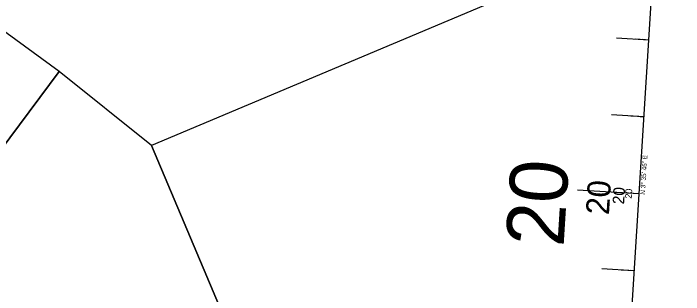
# Model space of a CAD drawing. Extents: x 2358865 to 2362945, y 393485 to 404880.
# Drawn here: x 2361585 to 2362454, y 402057 to 402421 of the extents above; entities that cross this region are included whole.
import ezdxf

# ---------------------------------------------------------------- set-up
doc = ezdxf.new("R2010")
doc.units = 0
for name, color, linetype in [('CL', 7, 'Continuous'), ('Level 11', 7, 'Continuous'), ('Level 19', 7, 'Continuous'), ('Level 21', 7, 'Continuous'), ('Level 25', 7, 'Continuous'), ('Level 27', 7, 'Continuous'), ('Level 30', 7, 'Continuous'), ('Level 37', 7, 'Continuous'), ('Level 39', 7, 'Continuous'), ('Level 41', 7, 'Continuous'), ('Level 48', 7, 'Continuous'), ('Level 63', 7, 'Continuous')]:
    doc.layers.add(name, color=color, linetype=linetype)

msp = doc.modelspace()

# ---------------------------------------------------------------- linework, layer by layer
at = {"layer": 'CL'}
msp.add_line((2362381, 401942.38), (2362564.78, 404866.59), dxfattribs=at)
msp.add_arc((2360608.55, 400955.34), 1370, 315.75191, 87.32696, dxfattribs=at)
at = {"layer": 'Level 11'}
msp.add_arc((2360631.17, 400937.8), 1389.46, 44.67453, 59.73673, dxfattribs=at)
at = {"layer": 'Level 19'}
for centre, radius, start, end in [((2360631.17, 400937.8), 1385.46, 44.67453, 59.73673), ((2360586.69, 400973.8), 1353.95, 42.30084, 57.36334)]:
    msp.add_arc(centre, radius, start, end, dxfattribs=at)
at = {"layer": 'Level 25'}
for p, q in [((2362408.93, 402386.76), (2362403.94, 402387.07)), ((2362402.66, 402286.96), (2362397.67, 402287.27)), ((2362396.38, 402187.15), (2362388.4, 402187.66)), ((2362390.11, 402087.35), (2362385.12, 402087.66))]:
    msp.add_line(p, q, dxfattribs=at)
at = {"layer": 'Level 27'}
msp.add_arc((2360608.55, 400955.34), 1310, 18.31889, 61.65271, dxfattribs=at)
at = {"layer": 'Level 30'}
for p, q in [((2362408.93, 402386.76), (2362400.44, 402387.29)), ((2362402.66, 402286.96), (2362394.17, 402287.49)), ((2362396.38, 402187.15), (2362380.41, 402188.16)), ((2362390.11, 402087.35), (2362381.63, 402087.88))]:
    msp.add_line(p, q, dxfattribs=at)
at = {"layer": 'Level 37'}
for centre, radius, start, end in [((2360586.69, 400973.8), 1365.95, 42.30084, 56.86254), ((2360631.17, 400937.8), 1373.46, 44.67453, 59.2385), ((2360586.69, 400973.8), 1366.45, 42.30084, 56.3574), ((2360631.17, 400937.8), 1372.96, 44.67453, 58.73575)]:
    msp.add_arc(centre, radius, start, end, dxfattribs=at)
at = {"layer": 'Level 39'}
for p, q in [((2362408.93, 402386.76), (2362391.96, 402387.83)), ((2362402.66, 402286.96), (2362385.69, 402288.02)), ((2362396.38, 402187.15), (2362364.45, 402189.16)), ((2362390.11, 402087.35), (2362373.14, 402088.42))]:
    msp.add_line(p, q, dxfattribs=at)
at = {"layer": 'Level 41'}
for p, q in [((2362408.93, 402386.76), (2362367.01, 402389.39)), ((2362402.66, 402286.96), (2362360.74, 402289.59)), ((2362396.38, 402187.15), (2362316.54, 402192.17)), ((2362390.11, 402087.35), (2362348.19, 402089.99))]:
    msp.add_line(p, q, dxfattribs=at)
at = {"layer": 'Level 48'}
for centre, radius, start, end in [((2360631.17, 400937.8), 1372.96, 44.67986, 58.73575), ((2360586.69, 400973.8), 1366.45, 42.3191, 56.3574)]:
    msp.add_arc(centre, radius, start, end, dxfattribs=at)
at = {"layer": 'Level 63'}
for points in [[(2359964.72, 401954.95), (2361163.38, 401700.43), (2361426.35, 402053.51), (2361426.35, 402053.51), (2361515.95, 402173.81), (2361644.31, 402346.15), (2361509.43, 402444.79), (2360042.14, 402756.34), (2359995.21, 402535.32), (2359995.21, 402535.32)], [(2362461.5, 402543.91), (2361764.38, 402249.82), (2362269.69, 401052.04), (2362944.62, 401336.78)], [(2361426.35, 402053.51), (2361146.52, 401677.8), (2361146.52, 401677.8), (2361497.41, 400807.35), (2361959.57, 400730.75), (2361959.57, 400730.75), (2362107.55, 400706.22), (2362344.68, 400666.91), (2362325.19, 400877.16), (2362269.69, 401052.04), (2361764.38, 402249.82), (2361644.31, 402346.15), (2361515.95, 402173.81)]]:
    msp.add_lwpolyline(points, close=True, dxfattribs=at)

# ---------------------------------------------------------------- texts
at = {"layer": 'Level 21'}
msp.add_text('N 3%%d 35\' 46" E', height=6, rotation=86.40384, dxfattribs=at).set_placement((2362403.83, 402186.02))
at = {"layer": 'Level 25'}
msp.add_text('20', height=8.75, rotation=86.40384, dxfattribs=at).set_placement((2362386.71, 402180.72))
at = {"layer": 'Level 30'}
msp.add_text('20', height=15, rotation=86.40384, dxfattribs=at).set_placement((2362376.78, 402173.3))
at = {"layer": 'Level 39'}
msp.add_text('20', height=30, rotation=86.40384, dxfattribs=at).set_placement((2362357.17, 402159.44))
at = {"layer": 'Level 41'}
msp.add_text('20', height=75, rotation=86.40384, dxfattribs=at).set_placement((2362298.33, 402117.67))

doc.saveas('drawing.dxf')
